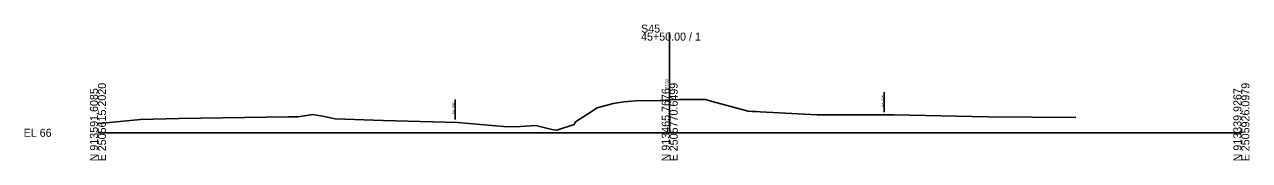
# Model space of a CAD drawing. Extents: x -26 to 403, y -10 to 17520.
# Drawn here: x -25.7 to 402.8, y 9490.3 to 9537.9 of the extents above; entities that cross this region are included whole.
import ezdxf

# ---------------------------------------------------------------- set-up
doc = ezdxf.new("R2010")
doc.units = 0
for name, color, linetype in [('RD_GPK_XS_Cell', 7, 'Continuous'), ('RD_XS_ExGround', 7, 'Continuous'), ('RD_XS_ExRW', 7, 'Continuous'), ('RD_XS_TX_Elev_EX', 7, 'Continuous')]:
    doc.layers.add(name, color=color, linetype=linetype)

msp = doc.modelspace()

# ---------------------------------------------------------------- linework, layer by layer
at = {"layer": 'RD_GPK_XS_Cell'}
for p, q in [((200, 9500), (200, 9535.04)), ((0, 9500), (200, 9500)), ((200, 9500), (400, 9500))]:
    msp.add_line(p, q, dxfattribs=at)
at = {"layer": 'RD_XS_ExGround'}
for p, q in [((174.65, 9508.74), (180.23, 9510.22)), ((180.23, 9510.22), (184, 9510.88)), ((184, 9510.88), (188.13, 9511.12)), ((188.13, 9511.12), (196.87, 9511.32)), ((196.87, 9511.32), (200, 9511.5)), ((200, 9511.5), (203.27, 9511.68)), ((203.27, 9511.68), (212.53, 9511.64)), ((212.53, 9511.64), (214.91, 9511)), ((214.91, 9511), (227.46, 9507.6)), ((14.91, 9504.69), (28.25, 9505.04)), ((28.25, 9505.04), (66.54, 9505.62)), ((66.54, 9505.62), (70, 9505.54)), ((70, 9505.54), (75.07, 9506.34)), ((75.07, 9506.34), (78.53, 9505.79)), ((78.53, 9505.79), (82.99, 9504.85)), ((82.99, 9504.85), (99.83, 9504.35)), ((167.02, 9503.81), (171.65, 9506.73)), ((171.65, 9506.73), (174.65, 9508.74)), ((227.46, 9507.6), (228.7, 9507.4)), ((228.7, 9507.4), (230.18, 9507.41)), ((230.18, 9507.41), (231.68, 9507.36)), ((231.68, 9507.36), (251.58, 9506.25)), ((251.58, 9506.25), (257.75, 9506.28)), ((257.75, 9506.28), (278.55, 9506.25)), ((278.55, 9506.25), (311.25, 9505.53)), ((311.25, 9505.53), (342.11, 9505.35)), ((0, 9503.26), (1.55, 9503.34)), ((1.55, 9503.34), (14.91, 9504.69)), ((99.83, 9504.35), (125.79, 9503.6)), ((125.79, 9503.6), (141.93, 9502.23)), ((141.93, 9502.23), (146.01, 9502.03)), ((146.01, 9502.03), (153.23, 9502.54)), ((153.23, 9502.54), (158.83, 9501.16)), ((158.83, 9501.16), (160.55, 9500.95)), ((160.55, 9500.95), (160.85, 9501.07)), ((160.85, 9501.07), (166.59, 9502.93)), ((166.59, 9502.93), (167.02, 9503.81))]:
    msp.add_line(p, q, dxfattribs=at)
at = {"layer": 'RD_XS_ExRW'}
for p, q in [((275, 9507.25), (275, 9514.25)), ((125, 9504.62), (125, 9511.62))]:
    msp.add_line(p, q, dxfattribs=at)

# ---------------------------------------------------------------- texts
at = {"layer": 'RD_GPK_XS_Cell'}
for s, p in [('45+50.00 / 1', (190, 9532.24)), ('S45', (190, 9535.04)), ('EL 66', (-26, 9498.6))]:
    msp.add_text(s, height=2.8, dxfattribs=at).set_placement(p)
for s, p in [('N 913591.6085', (0, 9490)), ('E 2505615.2020', (2.8, 9490)), ('N 913465.7676', (200, 9490)), ('E 2505770.6499', (202.8, 9490)), ('N 913339.9267', (400, 9490)), ('E 2505926.0979', (402.8, 9490))]:
    msp.add_text(s, height=2.8, rotation=90, dxfattribs=at).set_placement(p)
at = {"layer": 'RD_XS_ExRW'}
for p in [(124.75, 9506.58), (274.75, 9509.21)]:
    msp.add_text('EX. R/W ', height=0.75, rotation=90, dxfattribs=at).set_placement(p)
at = {"layer": 'RD_XS_TX_Elev_EX'}
msp.add_text('77.50', height=1, rotation=90, dxfattribs=at).set_placement((199.5, 9515.3))

doc.saveas('drawing.dxf')
